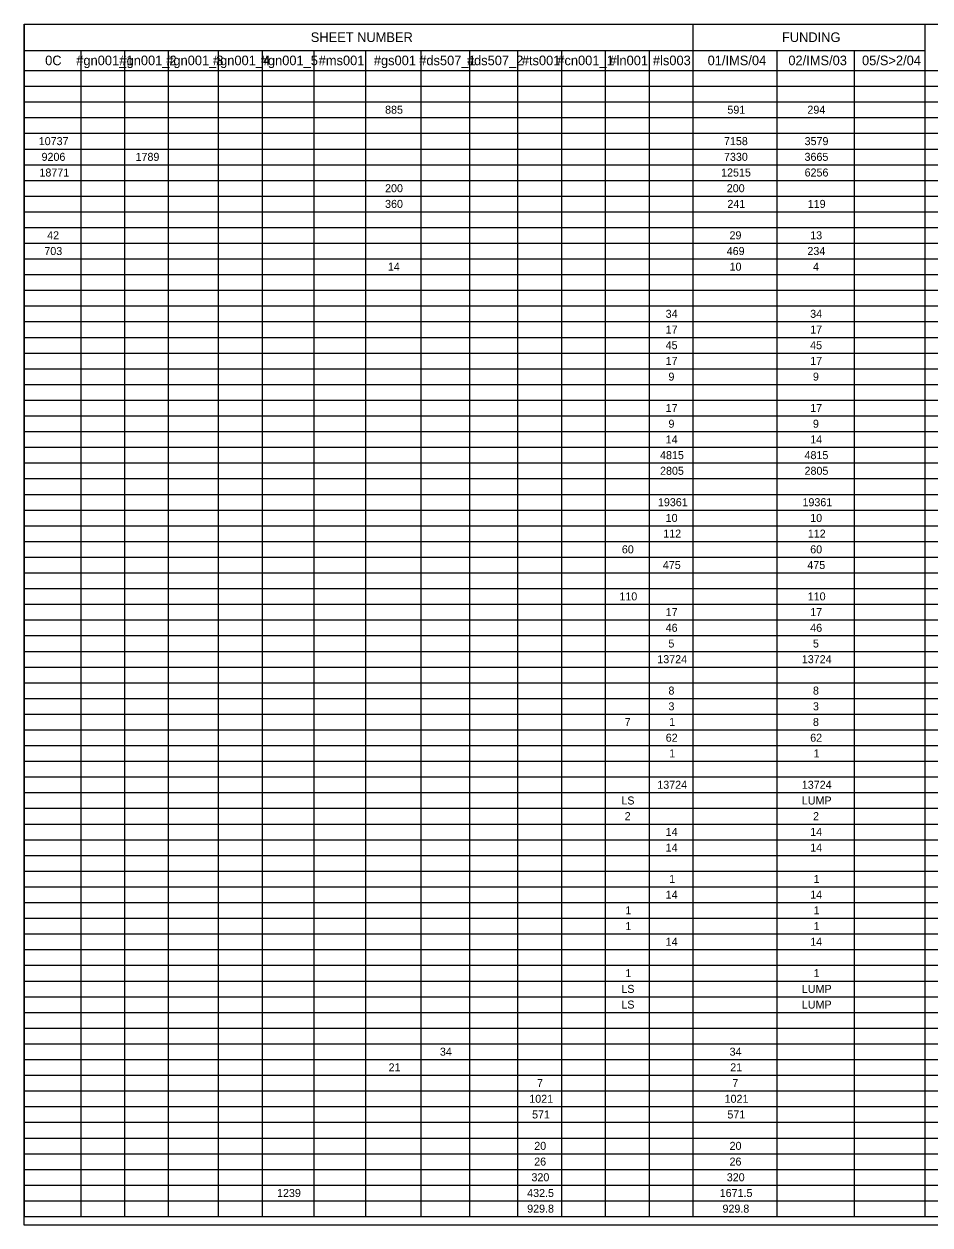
# Model space of a CAD drawing. Extents: x -542 to 295, y -281 to 32.
# Drawn here: x -416.42 to -400.58, y -100.59 to -79.59 of the extents above; entities that cross this region are included whole.
import ezdxf

# ---------------------------------------------------------------- set-up
doc = ezdxf.new("R2010")
doc.units = 0
for name, color, linetype in [('SC_Scratch1', 7, 'Continuous'), ('SH_Data', 7, 'Continuous'), ('SH_Text', 7, 'Continuous')]:
    doc.layers.add(name, color=color, linetype=linetype)

msp = doc.modelspace()

# ---------------------------------------------------------------- linework, layer by layer
at = {"layer": 'SC_Scratch1'}
msp.add_lwpolyline([(-416.421, -79.593), (-385.921, -79.593), (-385.921, -100.593), (-416.421, -100.593)], close=True, dxfattribs=at)
at = {"layer": 'SH_Data'}
for p, q in [((-416.419, -79.593), (-385.919, -79.593)), ((-416.419, -79.593), (-416.419, -100.444)), ((-404.723, -79.593), (-404.723, -100.444)), ((-400.669, -79.593), (-400.669, -100.444)), ((-416.419, -80.054), (-400.669, -80.054)), ((-415.429, -80.054), (-415.429, -100.444)), ((-414.663, -80.054), (-414.663, -100.444)), ((-413.897, -80.054), (-413.897, -100.444)), ((-413.024, -80.054), (-413.024, -100.444)), ((-412.258, -80.054), (-412.258, -100.444)), ((-411.353, -80.054), (-411.353, -100.444)), ((-410.449, -80.054), (-410.449, -100.444)), ((-409.48, -80.054), (-409.48, -100.444)), ((-408.629, -80.054), (-408.629, -100.444)), ((-407.788, -80.054), (-407.788, -100.444)), ((-407.022, -80.054), (-407.022, -100.444)), ((-406.256, -80.054), (-406.256, -100.444)), ((-405.49, -80.054), (-405.49, -100.444)), ((-403.255, -80.054), (-403.255, -100.444)), ((-401.903, -80.054), (-401.903, -100.444)), ((-416.419, -80.405), (-385.919, -80.405)), ((-416.419, -80.68), (-385.919, -80.68)), ((-416.419, -80.954), (-385.919, -80.954)), ((-416.419, -80.954), (-385.919, -80.954)), ((-416.419, -81.229), (-385.919, -81.229)), ((-416.419, -81.503), (-385.919, -81.503)), ((-416.419, -81.778), (-385.919, -81.778)), ((-416.419, -82.052), (-385.919, -82.052)), ((-416.419, -82.327), (-385.919, -82.327)), ((-416.419, -82.601), (-385.919, -82.601)), ((-416.419, -82.876), (-385.919, -82.876)), ((-416.419, -83.15), (-385.919, -83.15)), ((-416.419, -83.425), (-385.919, -83.425)), ((-416.419, -83.699), (-385.919, -83.699)), ((-416.419, -83.974), (-385.919, -83.974)), ((-416.419, -84.248), (-385.919, -84.248)), ((-416.419, -84.523), (-385.919, -84.523)), ((-416.419, -84.797), (-385.919, -84.797)), ((-416.419, -85.072), (-385.919, -85.072)), ((-416.419, -85.346), (-385.919, -85.346)), ((-416.419, -85.621), (-385.919, -85.621)), ((-416.419, -85.895), (-385.919, -85.895)), ((-416.419, -86.17), (-385.919, -86.17)), ((-416.419, -86.444), (-385.919, -86.444)), ((-416.419, -86.719), (-385.919, -86.719)), ((-416.419, -86.993), (-385.919, -86.993)), ((-416.419, -87.268), (-385.919, -87.268)), ((-416.419, -87.542), (-385.919, -87.542)), ((-416.419, -87.817), (-385.919, -87.817)), ((-416.419, -88.091), (-385.919, -88.091)), ((-416.419, -88.366), (-385.919, -88.366)), ((-416.419, -88.64), (-385.919, -88.64)), ((-416.419, -88.915), (-385.919, -88.915)), ((-416.419, -89.189), (-385.919, -89.189)), ((-416.419, -89.464), (-385.919, -89.464)), ((-416.419, -89.738), (-385.919, -89.738)), ((-416.419, -90.013), (-385.919, -90.013)), ((-416.419, -90.287), (-385.919, -90.287)), ((-416.419, -90.562), (-385.919, -90.562)), ((-416.419, -90.836), (-385.919, -90.836)), ((-416.419, -91.111), (-385.919, -91.111)), ((-416.419, -91.385), (-385.919, -91.385)), ((-416.419, -91.66), (-385.919, -91.66)), ((-416.419, -91.935), (-385.919, -91.935)), ((-416.419, -92.209), (-385.919, -92.209)), ((-416.419, -92.484), (-385.919, -92.484)), ((-416.419, -92.758), (-385.919, -92.758)), ((-416.419, -93.033), (-385.919, -93.033)), ((-416.419, -93.307), (-385.919, -93.307)), ((-416.419, -93.582), (-385.919, -93.582)), ((-416.419, -93.856), (-385.919, -93.856)), ((-416.419, -94.131), (-385.919, -94.131)), ((-416.419, -94.405), (-385.919, -94.405)), ((-416.419, -94.68), (-385.919, -94.68)), ((-416.419, -94.954), (-385.919, -94.954)), ((-416.419, -95.229), (-385.919, -95.229)), ((-416.419, -95.503), (-385.919, -95.503)), ((-416.419, -95.778), (-385.919, -95.778)), ((-416.419, -95.778), (-385.919, -95.778)), ((-416.419, -96.052), (-385.919, -96.052)), ((-416.419, -96.327), (-385.919, -96.327)), ((-416.419, -96.601), (-385.919, -96.601)), ((-416.419, -96.876), (-385.919, -96.876)), ((-416.419, -96.876), (-385.919, -96.876)), ((-416.419, -97.15), (-385.919, -97.15)), ((-416.419, -97.425), (-385.919, -97.425)), ((-416.419, -97.699), (-385.919, -97.699)), ((-416.419, -97.974), (-385.919, -97.974)), ((-416.419, -98.248), (-385.919, -98.248)), ((-416.419, -98.523), (-385.919, -98.523)), ((-416.419, -98.797), (-385.919, -98.797)), ((-416.419, -99.072), (-385.919, -99.072)), ((-416.419, -99.346), (-385.919, -99.346)), ((-416.419, -99.621), (-385.919, -99.621)), ((-416.419, -99.895), (-385.919, -99.895)), ((-416.419, -100.17), (-385.919, -100.17)), ((-416.419, -100.444), (-385.919, -100.444)), ((-416.419, -100.444), (-385.919, -100.444))]:
    msp.add_line(p, q, dxfattribs=at)

# ---------------------------------------------------------------- texts
at = {"layer": 'SH_Text'}
for s, height, p in [('SHEET NUMBER', 0.168, (-411.406, -79.907)), ('FUNDING', 0.168, (-403.165, -79.907)), ('0C', 0.168, (-416.051, -80.313)), ('#gn001_1', 0.168, (-415.507, -80.313)), ('#gn001_2', 0.168, (-414.752, -80.313)), ('#gn001_3', 0.168, (-413.933, -80.313)), ('#gn001_4', 0.168, (-413.116, -80.313)), ('#gn001_5', 0.168, (-412.28, -80.313)), ('#ms001', 0.168, (-411.267, -80.313)), ('#gs001', 0.168, (-410.303, -80.313)), ('#ds507_1', 0.168, (-409.509, -80.313)), ('#ds507_2', 0.168, (-408.675, -80.313)), ('#ts001', 0.168, (-407.715, -80.313)), ('#cn001_1', 0.168, (-407.094, -80.313)), ('#ln001', 0.168, (-406.182, -80.313)), ('#ls003', 0.168, (-405.422, -80.313)), ('01/IMS/04', 0.168, (-404.465, -80.313)), ('02/IMS/03', 0.168, (-403.053, -80.313)), ('05/S>2/04', 0.168, (-401.765, -80.313)), ('885', 0.14, (-410.106, -81.161)), ('591', 0.14, (-404.119, -81.161)), ('294', 0.14, (-402.72, -81.161)), ('10737', 0.14, (-416.163, -81.71)), ('7158', 0.14, (-404.179, -81.71)), ('3579', 0.14, (-402.769, -81.71)), ('9206', 0.14, (-416.114, -81.985)), ('1789', 0.14, (-414.47, -81.985)), ('7330', 0.14, (-404.179, -81.985)), ('3665', 0.14, (-402.77, -81.985)), ('18771', 0.14, (-416.151, -82.259)), ('12515', 0.14, (-404.229, -82.259)), ('6256', 0.14, (-402.769, -82.259)), ('200', 0.14, (-410.106, -82.534)), ('200', 0.14, (-404.13, -82.534)), ('360', 0.14, (-410.106, -82.808)), ('241', 0.14, (-404.119, -82.808)), ('119', 0.14, (-402.714, -82.808)), ('42', 0.14, (-416.016, -83.357)), ('29', 0.14, (-404.082, -83.357)), ('13', 0.14, (-402.671, -83.357)), ('703', 0.14, (-416.065, -83.632)), ('469', 0.14, (-404.131, -83.632)), ('234', 0.14, (-402.72, -83.632)), ('14', 0.14, (-410.057, -83.906)), ('10', 0.14, (-404.081, -83.906)), ('4', 0.14, (-402.622, -83.906)), ('34', 0.14, (-405.199, -84.73)), ('34', 0.14, (-402.671, -84.73)), ('17', 0.14, (-405.199, -85.005)), ('17', 0.14, (-402.671, -85.005)), ('45', 0.14, (-405.199, -85.279)), ('45', 0.14, (-402.672, -85.279)), ('17', 0.14, (-405.199, -85.554)), ('17', 0.14, (-402.671, -85.554)), ('9', 0.14, (-405.15, -85.828)), ('9', 0.14, (-402.623, -85.828)), ('17', 0.14, (-405.199, -86.377)), ('17', 0.14, (-402.671, -86.377)), ('9', 0.14, (-405.15, -86.652)), ('9', 0.14, (-402.623, -86.652)), ('14', 0.14, (-405.199, -86.926)), ('14', 0.14, (-402.671, -86.926)), ('4815', 0.14, (-405.297, -87.201)), ('4815', 0.14, (-402.77, -87.201)), ('2805', 0.14, (-405.297, -87.475)), ('2805', 0.14, (-402.77, -87.475)), ('19361', 0.14, (-405.334, -88.024)), ('19361', 0.14, (-402.806, -88.024)), ('10', 0.14, (-405.199, -88.299)), ('10', 0.14, (-402.671, -88.299)), ('112', 0.14, (-405.241, -88.573)), ('112', 0.14, (-402.713, -88.573)), ('60', 0.14, (-405.965, -88.848)), ('60', 0.14, (-402.671, -88.848)), ('475', 0.14, (-405.248, -89.122)), ('475', 0.14, (-402.721, -89.122)), ('110', 0.14, (-406.008, -89.671)), ('110', 0.14, (-402.714, -89.671)), ('17', 0.14, (-405.199, -89.946)), ('17', 0.14, (-402.671, -89.946)), ('46', 0.14, (-405.199, -90.22)), ('46', 0.14, (-402.671, -90.22)), ('5', 0.14, (-405.151, -90.495)), ('5', 0.14, (-402.623, -90.495)), ('13724', 0.14, (-405.345, -90.769)), ('13724', 0.14, (-402.818, -90.769)), ('8', 0.14, (-405.15, -91.318)), ('8', 0.14, (-402.623, -91.318)), ('3', 0.14, (-405.15, -91.593)), ('3', 0.14, (-402.623, -91.593)), ('7', 0.14, (-405.916, -91.867)), ('1', 0.14, (-405.138, -91.867)), ('8', 0.14, (-402.623, -91.867)), ('62', 0.14, (-405.198, -92.142)), ('62', 0.14, (-402.671, -92.142)), ('1', 0.14, (-405.138, -92.416)), ('1', 0.14, (-402.611, -92.416)), ('13724', 0.14, (-405.345, -92.965)), ('13724', 0.14, (-402.818, -92.965)), ('LS', 0.14, (-405.974, -93.24)), ('LUMP', 0.14, (-402.817, -93.24)), ('2', 0.14, (-405.916, -93.514)), ('2', 0.14, (-402.622, -93.514)), ('14', 0.14, (-405.199, -93.789)), ('14', 0.14, (-402.671, -93.789)), ('14', 0.14, (-405.199, -94.063)), ('14', 0.14, (-402.671, -94.063)), ('1', 0.14, (-405.138, -94.612)), ('1', 0.14, (-402.611, -94.612)), ('14', 0.14, (-405.199, -94.887)), ('14', 0.14, (-402.671, -94.887)), ('1', 0.14, (-405.904, -95.161)), ('1', 0.14, (-402.611, -95.161)), ('1', 0.14, (-405.904, -95.436)), ('1', 0.14, (-402.611, -95.436)), ('14', 0.14, (-405.199, -95.71)), ('14', 0.14, (-402.671, -95.71)), ('1', 0.14, (-405.904, -96.259)), ('1', 0.14, (-402.611, -96.259)), ('LS', 0.14, (-405.974, -96.534)), ('LUMP', 0.14, (-402.817, -96.534)), ('LS', 0.14, (-405.974, -96.808)), ('LUMP', 0.14, (-402.817, -96.808)), ('34', 0.14, (-409.147, -97.632)), ('34', 0.14, (-404.081, -97.632)), ('21', 0.14, (-410.045, -97.906)), ('21', 0.14, (-404.07, -97.906)), ('7', 0.14, (-407.449, -98.181)), ('7', 0.14, (-404.033, -98.181)), ('1021', 0.14, (-407.584, -98.456)), ('1021', 0.14, (-404.168, -98.456)), ('571', 0.14, (-407.535, -98.73)), ('571', 0.14, (-404.119, -98.73)), ('20', 0.14, (-407.497, -99.279)), ('20', 0.14, (-404.081, -99.279)), ('26', 0.14, (-407.498, -99.554)), ('26', 0.14, (-404.082, -99.554)), ('320', 0.14, (-407.546, -99.828)), ('320', 0.14, (-404.13, -99.828)), ('1239', 0.14, (-411.996, -100.103)), ('432.5', 0.14, (-407.621, -100.103)), ('1671.5', 0.14, (-404.254, -100.103)), ('929.8', 0.14, (-407.621, -100.377)), ('929.8', 0.14, (-404.205, -100.377))]:
    msp.add_text(s, height=height, dxfattribs=at).set_placement(p)

doc.saveas('drawing.dxf')
